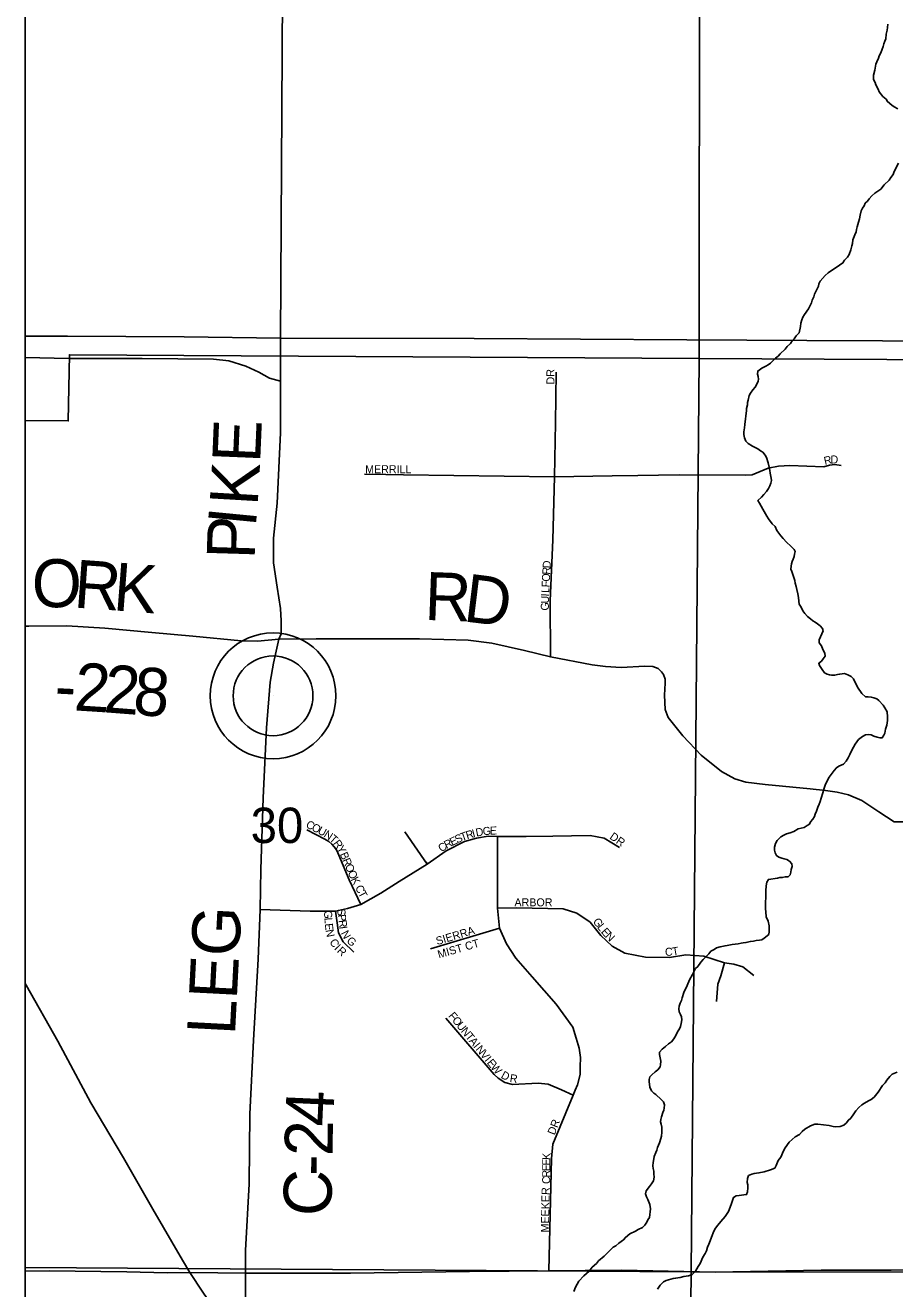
# Model space of a CAD drawing. Extents: x 8.5 to 81.5, y -1.2 to 22.4.
# Drawn here: x 49.453 to 50.481, y 16.747 to 18.242 of the extents above; entities that cross this region are included whole.
import ezdxf

# ---------------------------------------------------------------- set-up
doc = ezdxf.new("R2010")
doc.units = 0
for name, color, linetype in [('GM_X_County', 7, 'Continuous'), ('GM_X_County_Road', 7, 'Continuous'), ('GM_X_County_Road_Text', 7, 'Continuous'), ('GM_X_Interstate_Route', 7, 'Continuous'), ('GM_X_Minor_River', 7, 'Continuous'), ('GM_X_Section', 7, 'Continuous'), ('GM_X_Section_Text', 7, 'Continuous'), ('GM_X_Township', 7, 'Continuous'), ('GM_X_Township_Road', 7, 'Continuous'), ('GM_X_Township_Subdivision', 7, 'Continuous'), ('GM_X_Township_Subdivision_Text', 7, 'Continuous'), ('GM_X_Unincorporated', 7, 'Continuous'), ('GM_X_Unincorporated_Location', 7, 'Continuous'), ('SH_Data', 7, 'Continuous')]:
    doc.layers.add(name, color=color, linetype=linetype)

msp = doc.modelspace()

# ---------------------------------------------------------------- linework, layer by layer
at = {"layer": 'GM_X_County'}
msp.add_lwpolyline([(54.0879, 21.2506), (49.4527, 21.2506), (49.4527, 14.4506), (56.2527, 14.4506), (56.2527, 19.1108)], dxfattribs=at)
at = {"layer": 'GM_X_County_Road'}
for points in [[(49.7133, 16.6708), (49.7133, 16.7659), (49.7133, 16.7925), (49.7175, 16.8714), (49.7185, 16.9541), (49.7227, 17.0413), (49.7281, 17.1375), (49.7305, 17.1959), (49.7315, 17.2433), (49.734, 17.3281), (49.7382, 17.4111), (49.7423, 17.4651), (49.7464, 17.4873), (49.7526, 17.5158), (49.7555, 17.5223), (49.7555, 17.5377), (49.7548, 17.5523), (49.7506, 17.5772), (49.7465, 17.6063), (49.7465, 17.6353), (49.7506, 17.6768), (49.7548, 17.7599), (49.7548, 17.8209), (49.7548, 17.872), (49.7569, 18.2784)], [(49.4527, 17.5312), (49.457, 17.5312), (49.5018, 17.5318), (49.5468, 17.5288), (49.6024, 17.5239), (49.6509, 17.5193), (49.7083, 17.5137), (49.7275, 17.5134), (49.7526, 17.5158), (49.7968, 17.5164), (49.919, 17.5164), (49.9769, 17.5145), (50.0047, 17.511), (50.0433, 17.5024), (50.0743, 17.4951), (50.1234, 17.4857), (50.1394, 17.4836), (50.1579, 17.4824), (50.1857, 17.484), (50.1954, 17.4835), (50.2016, 17.4811), (50.2053, 17.4773), (50.208, 17.474), (50.2097, 17.4684), (50.2097, 17.4638), (50.2089, 17.4495), (50.2097, 17.4328), (50.2134, 17.4231), (50.2307, 17.4015), (50.2525, 17.3786), (50.2763, 17.3594), (50.2922, 17.3505), (50.3054, 17.3468), (50.3283, 17.3438), (50.3812, 17.3387), (50.3995, 17.337), (50.4133, 17.3349), (50.4268, 17.3319), (50.4427, 17.3249), (50.4626, 17.3116), (50.4807, 17.2998), (50.6306, 17.2998)], [(49.7133, 16.6708), (49.6892, 16.7047), (49.663, 16.7434), (49.6475, 16.7668), (49.6388, 16.7814), (49.6035, 16.8415), (49.569, 16.9023), (49.5302, 16.9672), (49.4912, 17.0405), (49.4536, 17.1067), (49.4527, 17.1086)]]:
    msp.add_lwpolyline(points, dxfattribs=at)
at = {"layer": 'GM_X_Interstate_Route'}
for points in [[(49.4527, 17.8744), (49.5028, 17.8743), (49.6409, 17.8734), (49.7548, 17.872), (49.9839, 17.8716), (50.2354, 17.8701), (50.3774, 17.8692), (50.467, 17.8689)], [(50.467, 17.8689), (50.6275, 17.8683), (50.7313, 17.8684), (50.9261, 17.8664), (50.9393, 17.8664), (50.9442, 17.8664)]]:
    msp.add_lwpolyline(points, dxfattribs=at)
at = {"layer": 'GM_X_Minor_River'}
for points in [[(50.485, 18.1433), (50.4809, 18.1457), (50.4779, 18.1476), (50.4727, 18.1519), (50.4712, 18.1546), (50.4675, 18.1577), (50.463, 18.1635), (50.462, 18.1666), (50.459, 18.1716), (50.4583, 18.1742), (50.4565, 18.1781), (50.4562, 18.183), (50.4579, 18.1891), (50.4591, 18.1959), (50.4603, 18.1989), (50.4623, 18.203), (50.4631, 18.2061), (50.4651, 18.2094), (50.4667, 18.214), (50.4679, 18.217), (50.4687, 18.22), (50.4696, 18.2234), (50.4708, 18.226), (50.4713, 18.2314), (50.4725, 18.2363), (50.4729, 18.2393), (50.4734, 18.2435)], [(50.4308, 17.981), (50.4313, 17.984), (50.4317, 17.9882), (50.4341, 17.9942), (50.4357, 17.9976), (50.4362, 18.0006), (50.437, 18.0036), (50.4378, 18.0063), (50.4386, 18.0093), (50.4398, 18.0131), (50.4407, 18.0176), (50.4419, 18.0225), (50.4435, 18.0259), (50.4451, 18.0286), (50.4463, 18.0316), (50.4494, 18.0342), (50.4513, 18.0368), (50.4544, 18.0405), (50.4579, 18.0435), (50.4648, 18.0483), (50.4691, 18.0535), (50.4749, 18.0587), (50.4769, 18.0621), (50.4796, 18.0655), (50.4808, 18.0693), (50.486, 18.079)], [(50.3614, 17.6107), (50.3626, 17.6137), (50.363, 17.6163), (50.3635, 17.6194), (50.3624, 17.622), (50.3587, 17.6259), (50.3534, 17.6306), (50.3494, 17.6348), (50.3468, 17.6383), (50.3442, 17.6414), (50.342, 17.6445), (50.3398, 17.6491), (50.3364, 17.6522), (50.332, 17.6584), (50.3302, 17.6614), (50.3287, 17.6641), (50.3254, 17.6695), (50.3214, 17.6768), (50.3195, 17.6799), (50.3238, 17.684), (50.3265, 17.687), (50.3296, 17.6907), (50.332, 17.6941), (50.3336, 17.6971), (50.3348, 17.7005), (50.3356, 17.7035), (50.3353, 17.7062), (50.3339, 17.7123), (50.3336, 17.7153), (50.3329, 17.7195), (50.3315, 17.7245), (50.3297, 17.7306), (50.3282, 17.7337), (50.3253, 17.7372), (50.3226, 17.7387), (50.3193, 17.7411), (50.3133, 17.7442), (50.308, 17.7474), (50.3054, 17.7501), (50.3036, 17.7539), (50.3029, 17.7578), (50.303, 17.7612), (50.3035, 17.7657), (50.3039, 17.7699), (50.3048, 17.7767), (50.3053, 17.7797), (50.3062, 17.7862), (50.3062, 17.7889), (50.3071, 17.793), (50.3071, 17.7957), (50.3079, 17.7987), (50.3092, 17.804), (50.3108, 17.807), (50.3135, 17.8107), (50.3162, 17.8141), (50.3178, 17.8167), (50.3198, 17.8209), (50.3202, 17.8235), (50.3199, 17.8266), (50.3192, 17.8293), (50.3193, 17.8331), (50.3243, 17.8364), (50.3289, 17.8389), (50.3316, 17.8404), (50.3343, 17.8423), (50.3405, 17.8482), (50.3435, 17.8508), (50.3459, 17.8534), (50.3517, 17.859), (50.354, 17.862), (50.3583, 17.8657), (50.3602, 17.8687), (50.3626, 17.8713), (50.3649, 17.8747), (50.3684, 17.8784), (50.3701, 17.8856), (50.3705, 17.8898), (50.3717, 17.8936), (50.3729, 17.8966), (50.3745, 17.9), (50.3796, 17.9067), (50.3808, 17.9097), (50.3828, 17.9139), (50.3836, 17.9169), (50.3856, 17.921), (50.3864, 17.9241), (50.388, 17.9271), (50.3912, 17.9335), (50.3916, 17.9361), (50.3932, 17.9395), (50.399, 17.9459), (50.4025, 17.9492), (50.4056, 17.9514), (50.4132, 17.9562), (50.4159, 17.9584), (50.4202, 17.961), (50.4221, 17.9644), (50.4256, 17.9678), (50.4276, 17.9708), (50.4296, 17.9764), (50.4308, 17.981)], [(50.3819, 17.2997), (50.3847, 17.3031), (50.3866, 17.3061), (50.3874, 17.3088), (50.389, 17.3125), (50.3906, 17.3171), (50.3919, 17.3208), (50.3931, 17.3239), (50.3943, 17.3276), (50.3963, 17.334), (50.3979, 17.3397), (50.3991, 17.3431), (50.4015, 17.3484), (50.4039, 17.3525), (50.4062, 17.3559), (50.4097, 17.3604), (50.4125, 17.3638), (50.4152, 17.3656), (50.4182, 17.3667), (50.4209, 17.3681), (50.424, 17.3715), (50.4264, 17.3753), (50.4283, 17.3794), (50.4303, 17.3839), (50.4327, 17.3881), (50.4347, 17.3918), (50.4386, 17.3971), (50.4432, 17.4008), (50.447, 17.4026), (50.4501, 17.4029), (50.4535, 17.4025), (50.4569, 17.4013), (50.4606, 17.4), (50.464, 17.3992), (50.4667, 17.3992), (50.4687, 17.4022), (50.4698, 17.4048), (50.4707, 17.4093), (50.4719, 17.4143), (50.4728, 17.4196), (50.4729, 17.4241), (50.4723, 17.4298), (50.4697, 17.4348), (50.4679, 17.4379), (50.4627, 17.4433), (50.4601, 17.4453), (50.4567, 17.4465), (50.4536, 17.4473), (50.4499, 17.4478), (50.4468, 17.4478), (50.4427, 17.4517), (50.4372, 17.459), (50.4325, 17.469), (50.4299, 17.4717), (50.4261, 17.4737), (50.422, 17.4753), (50.4163, 17.4746), (50.4136, 17.4739), (50.4105, 17.4732), (50.4067, 17.4733), (50.4041, 17.4737), (50.4015, 17.4746), (50.3985, 17.4761), (50.3955, 17.48), (50.3926, 17.4846), (50.3915, 17.4873), (50.3946, 17.4899), (50.3969, 17.4925), (50.3992, 17.4959), (50.3989, 17.4993), (50.3964, 17.5035), (50.3946, 17.5078), (50.392, 17.5116), (50.392, 17.515), (50.3968, 17.5256), (50.3961, 17.5286), (50.3932, 17.5317), (50.3902, 17.5341), (50.3872, 17.536), (50.3845, 17.5376), (50.3816, 17.5399), (50.3782, 17.5427), (50.3752, 17.5462), (50.3726, 17.5492), (50.3708, 17.5538), (50.3683, 17.5573), (50.3679, 17.5607), (50.3677, 17.5653), (50.3666, 17.5695), (50.3656, 17.5745), (50.3649, 17.5783), (50.3638, 17.5821), (50.3631, 17.5852), (50.3621, 17.589), (50.361, 17.5924), (50.3596, 17.5959), (50.3585, 17.5985), (50.3589, 17.6023), (50.3594, 17.605), (50.3602, 17.6076), (50.3614, 17.6107)], [(50.1908, 16.9923), (50.1909, 16.9949), (50.1917, 16.998), (50.194, 17.0006), (50.1979, 17.0039), (50.201, 17.0065), (50.2041, 17.0099), (50.2045, 17.0125), (50.2046, 17.0167), (50.2039, 17.0205), (50.2033, 17.0247), (50.2033, 17.0274), (50.2064, 17.0307), (50.2103, 17.0341), (50.2138, 17.0371), (50.2172, 17.0396), (50.22, 17.043), (50.2223, 17.0472), (50.2243, 17.0513), (50.2267, 17.055), (50.2278, 17.0577), (50.2287, 17.0611), (50.2295, 17.0656), (50.2292, 17.0691), (50.2281, 17.0717), (50.2263, 17.0752), (50.226, 17.0786), (50.2264, 17.0817), (50.2277, 17.0854), (50.2292, 17.0884), (50.2301, 17.0915), (50.2321, 17.0979), (50.2357, 17.1062), (50.2385, 17.113), (50.242, 17.119), (50.2459, 17.1261), (50.2483, 17.1287), (50.2522, 17.1336), (50.2549, 17.137), (50.2576, 17.1396), (50.2615, 17.1437), (50.2638, 17.1467), (50.2677, 17.1489), (50.2707, 17.1507), (50.2749, 17.1521), (50.2807, 17.1532), (50.2833, 17.1535), (50.289, 17.1545), (50.2963, 17.1555), (50.2997, 17.1562), (50.3023, 17.1565), (50.3054, 17.1569), (50.3107, 17.1583), (50.3142, 17.1586), (50.3176, 17.1593), (50.3214, 17.1596), (50.3241, 17.1603), (50.3271, 17.1621), (50.3325, 17.1666), (50.333, 17.17), (50.333, 17.1726), (50.3327, 17.1768), (50.3317, 17.1822), (50.3295, 17.1872), (50.3289, 17.1933), (50.3286, 17.1967), (50.329, 17.218), (50.3295, 17.224), (50.33, 17.2286), (50.332, 17.2316), (50.3426, 17.2333), (50.3453, 17.234), (50.3483, 17.2339), (50.3518, 17.2346), (50.3552, 17.2349), (50.3579, 17.2371), (50.3587, 17.2402), (50.3591, 17.2432), (50.36, 17.247), (50.3597, 17.25), (50.3571, 17.2531), (50.3537, 17.2551), (50.3507, 17.2559), (50.348, 17.2567), (50.3443, 17.2579), (50.3417, 17.2599), (50.3398, 17.263), (50.3391, 17.2664), (50.3392, 17.2698), (50.3404, 17.274), (50.3424, 17.2777), (50.3467, 17.2822), (50.3501, 17.284), (50.3532, 17.2855), (50.3578, 17.2869), (50.362, 17.2884), (50.367, 17.2913), (50.3742, 17.2931), (50.3777, 17.2953), (50.3804, 17.2971), (50.3819, 17.2997)], [(50.4619, 16.9801), (50.467, 16.9879), (50.4701, 16.9909), (50.472, 16.9943), (50.4755, 16.9984), (50.4783, 17.0014), (50.4844, 17.0036)], [(50.1019, 16.744), (50.1039, 16.7493), (50.1078, 16.7564), (50.1137, 16.7628), (50.1198, 16.7683), (50.1233, 16.7728), (50.1284, 16.7773), (50.1311, 16.7806), (50.1377, 16.7858), (50.1415, 16.7899), (50.1485, 16.7966), (50.1516, 16.7981), (50.155, 16.8015), (50.1604, 16.8051), (50.1628, 16.8081), (50.1682, 16.8122), (50.1747, 16.8155), (50.1778, 16.8177), (50.1831, 16.8199), (50.1858, 16.8225), (50.1882, 16.8263), (50.1894, 16.8289), (50.1913, 16.8319), (50.1918, 16.8353), (50.1922, 16.8383), (50.1923, 16.8418), (50.1917, 16.8471), (50.1895, 16.8532), (50.1877, 16.8563), (50.1866, 16.8597), (50.1874, 16.8631), (50.1913, 16.8684), (50.1937, 16.8714), (50.196, 16.8751), (50.1969, 16.8793), (50.1966, 16.8835), (50.1963, 16.8865), (50.1956, 16.8896), (50.1952, 16.893), (50.1957, 16.8968), (50.1965, 16.901), (50.197, 16.904), (50.1986, 16.9085), (50.1998, 16.9112), (50.2006, 16.9146), (50.203, 16.9202), (50.2046, 16.9251), (50.2054, 16.9278), (50.2059, 16.9327), (50.206, 16.9354), (50.2057, 16.9384), (50.205, 16.9422), (50.2043, 16.9449), (50.2047, 16.9475), (50.2055, 16.9509), (50.2072, 16.9559), (50.2084, 16.9585), (50.2088, 16.9611), (50.2092, 16.9649), (50.2078, 16.9684), (50.2052, 16.9715), (50.1989, 16.9773), (50.1963, 16.9789), (50.1937, 16.9816), (50.1915, 16.9858), (50.1912, 16.9896), (50.1908, 16.9923)], [(50.2006, 16.747), (50.2041, 16.7518), (50.208, 16.7556), (50.211, 16.757), (50.2191, 16.7595), (50.2221, 16.7598), (50.2274, 16.7609), (50.232, 16.7619), (50.2373, 16.7626), (50.2419, 16.7644), (50.2458, 16.7681), (50.249, 16.7737), (50.2513, 16.7771), (50.2545, 16.7847), (50.2572, 16.7892), (50.2588, 16.7922), (50.2601, 16.7967), (50.2613, 16.8001), (50.2632, 16.8042), (50.2648, 16.8084), (50.2673, 16.8156), (50.2692, 16.8189), (50.272, 16.8227), (50.2755, 16.8268), (50.2809, 16.8328), (50.2848, 16.8388), (50.288, 16.8471), (50.2896, 16.852), (50.2905, 16.8554), (50.2939, 16.8572), (50.2974, 16.8579), (50.3031, 16.8586), (50.3061, 16.8589), (50.3073, 16.8619), (50.3078, 16.8668), (50.3075, 16.8703), (50.3068, 16.8733), (50.3073, 16.8779), (50.3085, 16.8813), (50.3123, 16.8831), (50.3153, 16.8838), (50.3207, 16.8844), (50.3268, 16.8858), (50.3344, 16.888), (50.3394, 16.8901), (50.341, 16.8932), (50.3437, 16.8992), (50.3465, 16.9029), (50.35, 16.9105), (50.352, 16.9142), (50.3567, 16.921), (50.3637, 16.9273), (50.3687, 16.9298), (50.3718, 16.9336), (50.3749, 16.9362), (50.3818, 16.9402), (50.3871, 16.942), (50.3905, 16.942), (50.397, 16.9414), (50.4038, 16.9405), (50.4087, 16.9393), (50.4117, 16.9389), (50.4167, 16.9395), (50.4212, 16.941), (50.4243, 16.9436), (50.4263, 16.9466), (50.4294, 16.9492), (50.4329, 16.9544), (50.4356, 16.9578), (50.4391, 16.9619), (50.4426, 16.9649), (50.4457, 16.9671), (50.4503, 16.9696), (50.4537, 16.9715), (50.4572, 16.9741), (50.4619, 16.9801)]]:
    msp.add_lwpolyline(points, dxfattribs=at)
at = {"layer": 'GM_X_Section'}
for p, q in [((49.4527, 18.8647), (49.4527, 17.7746)), ((49.4527, 17.7746), (49.4527, 16.7724)), ((49.4527, 16.7724), (49.4527, 15.7683))]:
    msp.add_line(p, q, dxfattribs=at)
for points in [[(49.4527, 17.7746), (49.5035, 17.774), (49.505, 17.8523), (50.2502, 17.8478), (50.2509, 18.8543), (49.4527, 18.8647)], [(49.4527, 16.7724), (50.2406, 16.7675), (50.2502, 17.8478), (49.505, 17.8523), (49.5035, 17.774), (49.4527, 17.7746)], [(49.4527, 15.7683), (50.2298, 15.7659), (50.2406, 16.7675), (49.4527, 16.7724)]]:
    msp.add_lwpolyline(points, dxfattribs=at)
for points in [[(50.2509, 18.8543), (51.2202, 18.8578), (51.2117, 17.8427), (50.2502, 17.8478)], [(50.2502, 17.8478), (51.2117, 17.8427), (51.2044, 16.7664), (50.2406, 16.7675)], [(50.2406, 16.7675), (51.2044, 16.7664), (51.1955, 15.7645), (50.2298, 15.7659)]]:
    msp.add_lwpolyline(points, close=True, dxfattribs=at)
at = {"layer": 'GM_X_Township'}
msp.add_lwpolyline([(54.0879, 21.2506), (49.4527, 21.2506), (49.4527, 16.1615)], dxfattribs=at)
at = {"layer": 'GM_X_Township_Road'}
for points in [[(49.4527, 17.849), (49.5041, 17.848), (49.5911, 17.848), (49.6755, 17.8471), (49.6936, 17.8453), (49.7135, 17.839), (49.7289, 17.8317), (49.7416, 17.8245), (49.7548, 17.8209)], [(49.6478, 16.7668), (49.7133, 16.7659), (49.8375, 16.766), (49.9783, 16.7679), (50.072, 16.7686), (50.158, 16.7694), (50.2688, 16.767), (50.3944, 16.7695), (50.4772, 16.7693), (50.5134, 16.7701)], [(49.4527, 16.7681), (49.481, 16.7686), (49.5729, 16.7675), (49.6205, 16.7664), (49.6475, 16.7668), (49.6478, 16.7668)]]:
    msp.add_lwpolyline(points, dxfattribs=at)
at = {"layer": 'GM_X_Township_Subdivision'}
for points in [[(50.0743, 17.4951), (50.0738, 17.5614), (50.0769, 17.6335), (50.0789, 17.708), (50.0802, 17.7718), (50.0809, 17.8319)], [(50.1776, 17.7096), (50.2264, 17.7103), (50.3054, 17.71), (50.3127, 17.7102), (50.3315, 17.718), (50.3438, 17.7204), (50.3575, 17.7212), (50.3975, 17.7199), (50.4043, 17.7219), (50.4104, 17.7225), (50.418, 17.7213)], [(49.8541, 17.7109), (49.8795, 17.7105), (49.9001, 17.7103), (50.0789, 17.708), (50.1472, 17.7091)], [(50.1472, 17.7091), (50.1776, 17.7096)], [(49.7305, 17.1959), (49.7899, 17.1941), (49.8198, 17.1941), (49.8341, 17.1974), (49.8496, 17.202), (49.8736, 17.2152), (49.8951, 17.229), (49.9281, 17.2498), (49.9509, 17.2656), (49.9726, 17.2767), (49.9868, 17.2805), (50.0003, 17.2828), (50.0114, 17.2824), (50.0275, 17.2824), (50.0452, 17.2824), (50.0771, 17.2828), (50.1212, 17.2835), (50.1378, 17.2804), (50.1559, 17.2694)], [(49.8496, 17.202), (49.8359, 17.2311), (49.8237, 17.2602), (49.8225, 17.2631), (49.8208, 17.2665), (49.8181, 17.2702), (49.8156, 17.2733), (49.812, 17.2765), (49.8073, 17.2794), (49.7857, 17.2903)], [(49.9269, 17.2525), (49.9281, 17.2498), (49.902, 17.2881)], [(50.072, 16.7686), (50.0754, 16.9014), (50.0768, 16.9185), (50.1011, 16.9765), (50.1035, 16.9822), (50.1061, 16.9887), (50.1091, 17.0007), (50.1094, 17.01), (50.1096, 17.0211), (50.1081, 17.0322), (50.1044, 17.044), (50.1004, 17.0568), (50.0807, 17.084), (50.0526, 17.1166), (50.0333, 17.1386), (50.022, 17.1553), (50.0137, 17.1738), (50.0114, 17.1976), (50.0114, 17.2824)], [(49.8413, 17.1455), (49.8287, 17.158), (49.8233, 17.1684), (49.8217, 17.1803), (49.8198, 17.1941)], [(50.0114, 17.1976), (50.0345, 17.1979), (50.0892, 17.1968), (50.1054, 17.1917), (50.1209, 17.1812), (50.1339, 17.1652), (50.1472, 17.1525), (50.1621, 17.1445), (50.1867, 17.1398), (50.2151, 17.1392), (50.2343, 17.1423), (50.2556, 17.141), (50.2799, 17.1328), (50.2911, 17.1313), (50.3016, 17.1282), (50.3146, 17.1179)], [(49.9321, 17.1494), (50.0137, 17.1738)], [(50.2799, 17.1328), (50.2758, 17.1175), (50.2722, 17.1078), (50.2707, 17.0873)], [(49.9503, 17.0677), (50.0076, 17.0009), (50.0124, 16.9964), (50.0203, 16.9913), (50.0292, 16.9892), (50.0596, 16.9907), (50.0713, 16.9896), (50.0872, 16.9827), (50.1011, 16.9765)]]:
    msp.add_lwpolyline(points, dxfattribs=at)
at = {"layer": 'GM_X_Unincorporated'}
for radius in [0.0744, 0.0472]:
    msp.add_circle((49.7459, 17.4489), radius, dxfattribs=at)
at = {"layer": 'GM_X_Unincorporated_Location'}
msp.add_line((49.7459, 17.4489), (49.7459, 17.4489), dxfattribs=at)
at = {"layer": 'SH_Data'}
msp.add_line((49.4527, 21.2506), (49.4527, 14.4506), dxfattribs=at)

# ---------------------------------------------------------------- texts
at = {"layer": 'GM_X_County_Road_Text'}
for s, height, rotation, p in [('E', 0.0568, 87.6044, (49.7306, 17.7238)), ('K', 0.0568, 86.6439, (49.7276, 17.6729)), ('I', 0.0568, 84.496, (49.7252, 17.6474)), ('P', 0.0568, 88.2464, (49.7241, 17.61)), ('O', 0.0568, 359.1476, (49.4601, 17.5541)), ('R', 0.0568, 355.9491, (49.5092, 17.5534)), ('K', 0.0568, 355.5661, (49.5557, 17.5501)), ('R', 0.0568, 357.9623, (49.9246, 17.5387)), ('D', 0.0568, 352.9848, (49.9699, 17.5371)), ('2', 0.0568, 356.3497, (49.5096, 17.4317)), ('2', 0.0568, 355.6141, (49.5444, 17.4295)), ('8', 0.0568, 355.4157, (49.5792, 17.4269)), ('-', 0.0568, 357.1263, (49.4865, 17.4329)), ('LEG', 0.05682, 87.0374, (49.7008, 17.0468)), ('4', 0.0568, 87.4596, (49.8168, 16.9386)), ('2', 0.0568, 89.2945, (49.8163, 16.9041)), ('-', 0.0568, 89.2592, (49.816, 16.8807)), ('C', 0.0568, 87.8215, (49.8142, 16.8325))]:
    msp.add_text(s, height=height, rotation=rotation, dxfattribs=at).set_placement(p)
at = {"layer": 'GM_X_Section_Text'}
msp.add_text('30', height=0.04186, rotation=0, dxfattribs=at).set_placement((49.7194, 17.2747))
at = {"layer": 'GM_X_Township_Subdivision_Text'}
for s, rotation, p in [('DR', 90, (50.0788, 17.8172)), ('R', 13.2294, (50.3988, 17.7219)), ('D', 1.7271, (50.4056, 17.7236)), ('MERRILL', 0, (49.8548, 17.7122)), ('D', 87.0091, (50.0742, 17.5995)), ('O', 86.9981, (50.0733, 17.5837)), ('R', 86.9987, (50.0738, 17.592)), ('F', 86.9987, (50.073, 17.577)), ('U', 88.251, (50.0722, 17.5579)), ('I', 87.1136, (50.0724, 17.5662)), ('L', 86.9929, (50.0726, 17.5704)), ('G', 89.9126, (50.0722, 17.5497)), ('C', 332.2403, (49.7839, 17.2938)), ('O', 332.2514, (49.7906, 17.2903)), ('U', 332.2425, (49.7979, 17.2864)), ('G', 6.9678, (49.9945, 17.2837)), ('E', 0.8743, (50.0025, 17.2847)), ('N', 326.8918, (49.8051, 17.2826)), ('T', 319.0017, (49.8118, 17.2783)), ('R', 306.1024, (49.8165, 17.2743)), ('R', 27.8468, (49.9511, 17.2676)), ('E', 26.3939, (49.9577, 17.271)), ('S', 25.9662, (49.9637, 17.274)), ('T', 19.9387, (49.9694, 17.2768)), ('R', 16.6527, (49.9755, 17.279)), ('I', 14.768, (49.9826, 17.2812)), ('D', 10.6156, (49.9865, 17.2822)), ('DR', 325.495, (50.1433, 17.2803)), ('Y', 299.4304, (49.8207, 17.2685)), ('B', 293.9576, (49.8247, 17.2615)), ('C', 34.5723, (49.9452, 17.2635)), ('R', 292.902, (49.8277, 17.2546)), ('O', 292.8771, (49.8307, 17.2477)), ('O', 293.5488, (49.834, 17.24)), ('K', 297.1294, (49.8376, 17.2317)), ('C', 297.9038, (49.8426, 17.222)), ('T', 297.8964, (49.8461, 17.2154)), ('ARBOR', 0, (50.0315, 17.1998)), ('G', 273.2805, (49.8061, 17.1947)), ('S', 277.369, (49.8216, 17.1965)), ('P', 277.4108, (49.8224, 17.1898)), ('L', 274.1934, (49.8066, 17.1862)), ('E', 276.4093, (49.8071, 17.1792)), ('R', 277.378, (49.8233, 17.1832)), ('I', 277.4155, (49.8242, 17.1758)), ('SIERRA', 16.587, (49.9401, 17.1539)), ('G', 307.9804, (50.1237, 17.1816)), ('L', 308.0001, (50.1288, 17.175)), ('E', 311.4138, (50.1333, 17.1693)), ('N', 281.4565, (49.808, 17.1716)), ('C', 300.3141, (49.8123, 17.158)), ('N', 297.7286, (49.8259, 17.1682)), ('G', 318.4608, (49.8321, 17.1579)), ('MIST CT', 16.0907, (49.9421, 17.1382)), ('N', 315.3015, (50.1382, 17.1638)), ('I', 314.2206, (49.8176, 17.1495)), ('R', 317.2047, (49.8209, 17.1462)), ('C', 359.4414, (50.2095, 17.1414)), ('T', 10.0468, (50.2189, 17.1415)), ('F', 309.3125, (49.9528, 17.07)), ('O', 309.3186, (49.9571, 17.0648)), ('U', 309.3186, (49.9623, 17.0584)), ('N', 309.2879, (49.9676, 17.0519)), ('T', 309.3331, (49.9729, 17.0455)), ('A', 309.3276, (49.9771, 17.0403)), ('I', 309.274, (49.9824, 17.0339)), ('N', 309.3117, (49.9851, 17.0306)), ('V', 309.3186, (49.9903, 17.0242)), ('I', 309.3017, (49.9956, 17.0177)), ('E', 309.2983, (49.9983, 17.0145)), ('W', 310.8801, (50.0027, 17.0091)), ('D', 331.3453, (50.0147, 16.9973)), ('R', 351.8685, (50.0255, 16.9921)), ('DR', 68.7471, (50.079, 16.9286)), ('K', 87.9889, (50.0739, 16.8996)), ('E', 89.7268, (50.0738, 16.893)), ('E', 89.9727, (50.0738, 16.8863)), ('C', 89.9757, (50.0738, 16.8713)), ('R', 89.9703, (50.0738, 16.8788)), ('MEEKER', 88.9954, (50.0722, 16.8139))]:
    msp.add_text(s, height=0.00947, rotation=rotation, dxfattribs=at).set_placement(p)

doc.saveas('drawing.dxf')
